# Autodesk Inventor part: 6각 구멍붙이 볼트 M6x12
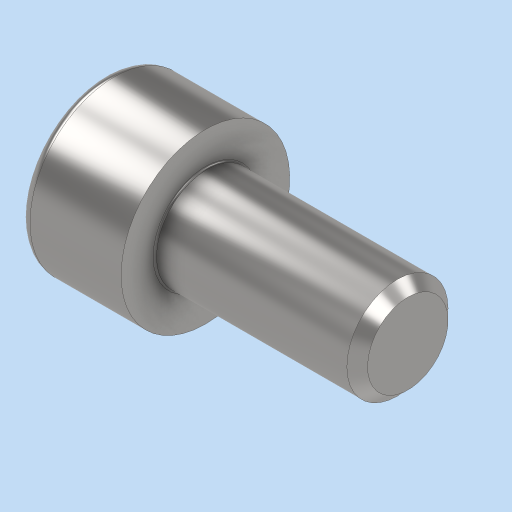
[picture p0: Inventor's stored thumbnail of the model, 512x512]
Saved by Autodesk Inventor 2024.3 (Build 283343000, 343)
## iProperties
Created: 2026-01
Part Number: 6각 구멍붙이 볼트 M6x12
Material: 강철, 연강
Description: 6각머리 태핑 나사
Document SubType Name: Modeling
Designer: PC2-02
Density: 7.85 g/cm^3
Appearance: 기본값
Author: jhkim
Sending System: Autodesk Inventor 2026
Preprocessor: ST-DEVELOPER v20.1
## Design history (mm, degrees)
node "6각 구멍붙이 볼트 M6x121"
node "솔리드1"
body "Solid1"
